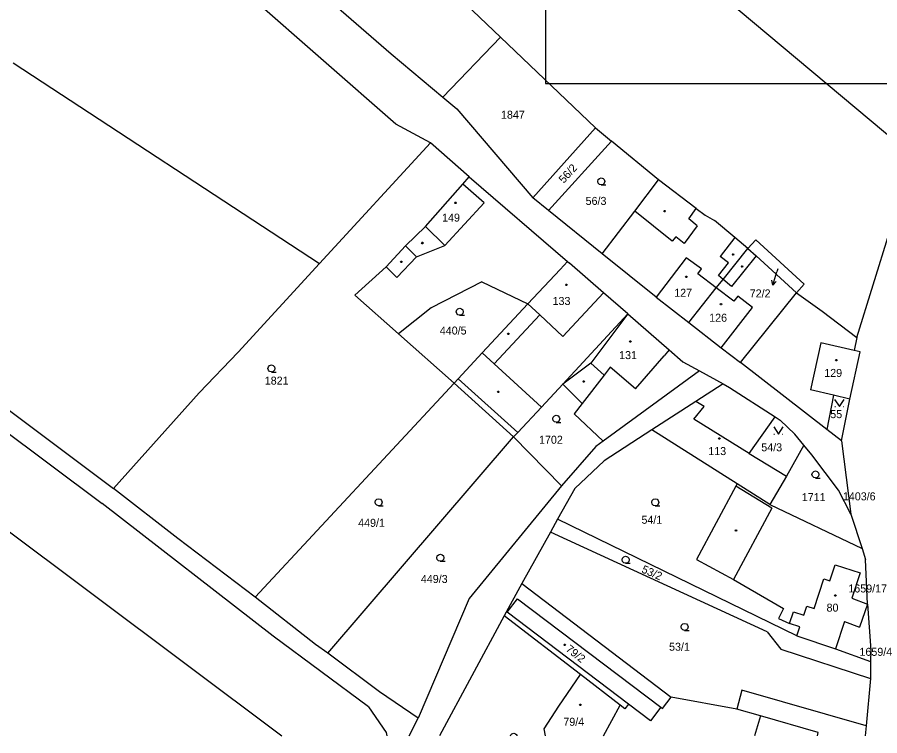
# Model space of a CAD drawing. Extents: x -801853 to -800578, y -1017479 to -1016338.
# Drawn here: x -801671.4 to -801488.1, y -1017477.7 to -1017325 of the extents above; entities that cross this region are included whole.
import ezdxf

# ---------------------------------------------------------------- set-up
doc = ezdxf.new("R2010")
doc.units = 0
for name, color, linetype in [('Default', 7, 'Continuous'), ('KN_HRANICE', 7, 'Continuous'), ('KN_KULTURY', 7, 'Continuous'), ('KN_PARCELY', 7, 'Continuous'), ('KN_SLUCKY', 7, 'Continuous'), ('LEGENDA', 7, 'Continuous')]:
    doc.layers.add(name, color=color, linetype=linetype)

# ---------------------------------------------------------------- blocks, each defined once
blk = doc.blocks.new('304')
at = {"layer": 'Default'}
blk.add_lwpolyline([(0, 0), (-0.38, 0.1), (-0.65, 0.37), (-0.75, 0.74), (-0.65, 1.11), (-0.38, 1.38), (-0.01, 1.48), (0.36, 1.38), (0.63, 1.11), (0.73, 0.73), (0.63, 0.35), (0.36, 0.08), (-0.02, -0.02), (0.98, -0.02)], dxfattribs=at)
blk = doc.blocks.new('314')
at = {"layer": 'Default'}
for p, q in [((-0.95, 0), (-0.85, 0)), ((0.85, 0), (0.95, 0))]:
    blk.add_line(p, q, dxfattribs=at)
blk.add_lwpolyline([(-1, 1.5), (0, 0), (1, 1.5)], dxfattribs=at)
blk = doc.blocks.new('NAHRADNI_SYMBOL')
at = {"layer": 'Default'}
blk.add_lwpolyline([(0.09, 0.15), (0.18, 0), (0.09, -0.15), (-0.09, -0.15), (-0.18, 0), (-0.09, 0.15), (0.09, 0.15)], dxfattribs=at)
blk = doc.blocks.new('10292')
at = {"layer": 'Default'}
blk.add_line((0, 3), (0, 0), dxfattribs=at)
blk.add_lwpolyline([(-0.5, 2), (0, 3), (0.5, 2)], dxfattribs=at)
blk = doc.blocks.new('402')
at = {"layer": 'Default'}
blk.add_lwpolyline([(0.09, 0.15), (0.18, 0), (0.09, -0.15), (-0.09, -0.15), (-0.18, 0), (-0.09, 0.15), (0.09, 0.15)], dxfattribs=at)

msp = doc.modelspace()

# ---------------------------------------------------------------- linework, layer by layer
at = {"layer": 'KN_HRANICE'}
for p, q in [((-801619.51, -1017238.39), (-801481.95, -1017353.71)), ((-801617.81, -1017310.3), (-801591.97, -1017332.75)), ((-801802.71, -1017316.54), (-801653.38, -1017428.3)), ((-801568.75, -1017329.21), (-801579.02, -1017319.41)), ((-801590.96, -1017347.71), (-801622.51, -1017320.08)), ((-801568.75, -1017329.21), (-801580.94, -1017341.98)), ((-801548.54, -1017348.49), (-801568.75, -1017329.21)), ((-801591.97, -1017332.75), (-801580.94, -1017341.98)), ((-801771.82, -1017334.66), (-801650.93, -1017425.14)), ((-801672.29, -1017334.66), (-801607.17, -1017377.34)), ((-801580.94, -1017341.98), (-801577.98, -1017344.46)), ((-801577.98, -1017344.46), (-801561.84, -1017363.38)), ((-801583.62, -1017351.71), (-801590.96, -1017347.71)), ((-801561.84, -1017363.38), (-801548.54, -1017348.49)), ((-801548.54, -1017348.49), (-801545.1, -1017351.32)), ((-801607.17, -1017377.34), (-801583.62, -1017351.71)), ((-801575.39, -1017358.89), (-801583.62, -1017351.71)), ((-801558.54, -1017366.04), (-801545.1, -1017351.32)), ((-801535.15, -1017359.53), (-801545.1, -1017351.32)), ((-801576.74, -1017360.44), (-801575.39, -1017358.89)), ((-801575.39, -1017358.89), (-801554.48, -1017376.92)), ((-801540.19, -1017366.17), (-801535.15, -1017359.53)), ((-801527.11, -1017365.64), (-801535.15, -1017359.53)), ((-801584.63, -1017369.48), (-801576.74, -1017360.44)), ((-801558.54, -1017366.04), (-801561.84, -1017363.38)), ((-801547.08, -1017375.26), (-801558.54, -1017366.04)), ((-801547.08, -1017375.26), (-801540.19, -1017366.17)), ((-801527.11, -1017365.64), (-801525.25, -1017367.08)), ((-801525.25, -1017367.08), (-801523.25, -1017368.15)), ((-801518.94, -1017371.78), (-801523.25, -1017368.15)), ((-801588.89, -1017373.59), (-801584.63, -1017369.48)), ((-801493.03, -1017393.07), (-801486.04, -1017370.69)), ((-801516.17, -1017374.11), (-801518.94, -1017371.78)), ((-801514.48, -1017372.27), (-801516.17, -1017374.11)), ((-801514.48, -1017372.27), (-801504.16, -1017381.72)), ((-801592.99, -1017378.06), (-801588.89, -1017373.59)), ((-801521.42, -1017380.69), (-801516.17, -1017374.11)), ((-801516.17, -1017374.11), (-801514.41, -1017375.72)), ((-801535.63, -1017384.47), (-801547.08, -1017375.26)), ((-801514.41, -1017375.72), (-801505.85, -1017383.57)), ((-801624.47, -1017396.18), (-801607.17, -1017377.34)), ((-801599.68, -1017384.03), (-801592.99, -1017378.06)), ((-801556.07, -1017378.59), (-801554.48, -1017376.92)), ((-801554.48, -1017376.92), (-801554.09, -1017377.25)), ((-801546.85, -1017383.57), (-801554.09, -1017377.25)), ((-801562.88, -1017385.9), (-801556.07, -1017378.59)), ((-801572.67, -1017381.19), (-801583.43, -1017386.73)), ((-801572.67, -1017381.19), (-801562.88, -1017385.9)), ((-801522.87, -1017382.51), (-801521.42, -1017380.69)), ((-801504.16, -1017381.72), (-801505.85, -1017383.57)), ((-801541.65, -1017388.03), (-801546.85, -1017383.57)), ((-801528.72, -1017389.84), (-801522.87, -1017382.51)), ((-801517.7, -1017398.38), (-801505.85, -1017383.57)), ((-801505.85, -1017383.57), (-801500.35, -1017387.46)), ((-801590.38, -1017392.28), (-801599.68, -1017384.03)), ((-801535.63, -1017384.47), (-801528.72, -1017389.84)), ((-801583.43, -1017386.73), (-801590.38, -1017392.28)), ((-801572.59, -1017396.33), (-801562.88, -1017385.9)), ((-801555.48, -1017402.95), (-801541.65, -1017388.03)), ((-801541.65, -1017388.03), (-801532.86, -1017395.69)), ((-801500.35, -1017387.46), (-801493.03, -1017393.07)), ((-801528.72, -1017389.84), (-801521.8, -1017395.21)), ((-801578.57, -1017402.75), (-801590.38, -1017392.28)), ((-801493.03, -1017393.07), (-801493.56, -1017395.81)), ((-801632.76, -1017404.81), (-801624.47, -1017396.18)), ((-801577.72, -1017401.84), (-801572.59, -1017396.33)), ((-801532.86, -1017395.69), (-801529.98, -1017398.2)), ((-801521.8, -1017395.21), (-801517.7, -1017398.38)), ((-801494.46, -1017406.11), (-801492.26, -1017396.11)), ((-801492.26, -1017396.11), (-801493.56, -1017395.81)), ((-801529.98, -1017398.2), (-801526.45, -1017400.14)), ((-801526.45, -1017400.14), (-801546.89, -1017415.08)), ((-801526.45, -1017400.14), (-801521.42, -1017402.91)), ((-801499.39, -1017412.56), (-801517.7, -1017398.38)), ((-801717.22, -1017401.3), (-801615.2, -1017477.65)), ((-801578.57, -1017402.75), (-801577.72, -1017401.84)), ((-801578.57, -1017402.75), (-801620.86, -1017448.21)), ((-801578.57, -1017402.75), (-801565.92, -1017414.14)), ((-801560.03, -1017407.86), (-801555.48, -1017402.95)), ((-801551.33, -1017407.06), (-801555.48, -1017402.95)), ((-801521.42, -1017402.91), (-801527.19, -1017406.63)), ((-801521.42, -1017402.91), (-801520.08, -1017403.65)), ((-801520.08, -1017403.65), (-801510.35, -1017409.92)), ((-801650.93, -1017425.14), (-801632.76, -1017404.81)), ((-801497.98, -1017405.3), (-801499.39, -1017412.56)), ((-801494.46, -1017406.11), (-801497.98, -1017405.3)), ((-801551.33, -1017407.06), (-801553.03, -1017409.26)), ((-801527.19, -1017406.63), (-801536.56, -1017412.68)), ((-801496.25, -1017414.99), (-801494.46, -1017406.11)), ((-801565.05, -1017413.25), (-801560.03, -1017407.86)), ((-801553.03, -1017409.26), (-801546.89, -1017415.08)), ((-801515.86, -1017417.69), (-801510.35, -1017409.92)), ((-801510.35, -1017409.92), (-801509.28, -1017410.61)), ((-801506.17, -1017413.59), (-801509.28, -1017410.61)), ((-801536.56, -1017412.68), (-801546.71, -1017419.24)), ((-801518.43, -1017424.13), (-801536.56, -1017412.68)), ((-801496.25, -1017414.99), (-801499.39, -1017412.56)), ((-801605.43, -1017460.13), (-801565.92, -1017414.14)), ((-801565.92, -1017414.14), (-801565.05, -1017413.25)), ((-801565.92, -1017414.14), (-801555.75, -1017424.58)), ((-801504.24, -1017415.93), (-801506.17, -1017413.59)), ((-801548.47, -1017416.23), (-801555.75, -1017424.58)), ((-801546.89, -1017415.08), (-801548.47, -1017416.23)), ((-801504.24, -1017415.93), (-801507.97, -1017422.53)), ((-801502.53, -1017418), (-801504.24, -1017415.93)), ((-801496.25, -1017414.99), (-801494.3, -1017430.54)), ((-801515.86, -1017417.69), (-801507.97, -1017422.53)), ((-801496.87, -1017425.51), (-801502.53, -1017418)), ((-801546.71, -1017419.24), (-801552.91, -1017425.1)), ((-801507.97, -1017422.53), (-801511.47, -1017428.53)), ((-801637.26, -1017435.75), (-801650.93, -1017425.14)), ((-801555.75, -1017424.58), (-801575.39, -1017448.51)), ((-801552.91, -1017425.1), (-801556.57, -1017431.67)), ((-801518.7, -1017424.64), (-801527.1, -1017440.22)), ((-801518.43, -1017424.13), (-801518.7, -1017424.64)), ((-801511.47, -1017428.53), (-801518.43, -1017424.13)), ((-801494.3, -1017430.54), (-801496.87, -1017425.51)), ((-801617.04, -1017456.51), (-801653.38, -1017428.3)), ((-801511.47, -1017428.53), (-801491.9, -1017437.9)), ((-801494.3, -1017430.54), (-801491.9, -1017437.9)), ((-801556.57, -1017431.67), (-801558.1, -1017434.4)), ((-801505.75, -1017456.45), (-801556.57, -1017431.67)), ((-801558.1, -1017434.4), (-801564.2, -1017445.34)), ((-801512.08, -1017455.55), (-801558.1, -1017434.4)), ((-801620.86, -1017448.21), (-801637.26, -1017435.75)), ((-801491.9, -1017437.9), (-801491.16, -1017440.19)), ((-801527.1, -1017440.22), (-801519.19, -1017444.45)), ((-801490.73, -1017449.68), (-801491.16, -1017440.19)), ((-801564.2, -1017445.34), (-801567.91, -1017452.2)), ((-801564.2, -1017445.34), (-801532.43, -1017469.46)), ((-801519.19, -1017444.45), (-801508.59, -1017450.64)), ((-801608.02, -1017458.26), (-801620.86, -1017448.21)), ((-801575.39, -1017448.51), (-801586.22, -1017473.94)), ((-801508.59, -1017450.64), (-801509.67, -1017452.75)), ((-801490.73, -1017449.68), (-801490.02, -1017459.44)), ((-801567.91, -1017452.2), (-801581.66, -1017477.65)), ((-801551.71, -1017464.66), (-801567.91, -1017452.2)), ((-801509.67, -1017452.75), (-801507.29, -1017453.78)), ((-801505.11, -1017454.5), (-801507.29, -1017453.78)), ((-801505.75, -1017456.45), (-801505.11, -1017454.5)), ((-801596.78, -1017471.51), (-801617.04, -1017456.51)), ((-801512.08, -1017455.55), (-801509.17, -1017459.29)), ((-801505.75, -1017456.45), (-801497.54, -1017459.17)), ((-801605.43, -1017460.13), (-801608.02, -1017458.26)), ((-801594.4, -1017468.3), (-801605.43, -1017460.13)), ((-801509.17, -1017459.29), (-801490.11, -1017465.48)), ((-801497.54, -1017459.17), (-801490.11, -1017461.87)), ((-801490.02, -1017459.44), (-801490.11, -1017461.87)), ((-801490.11, -1017461.87), (-801490.11, -1017465.48)), ((-801556.33, -1017471.36), (-801551.71, -1017464.66)), ((-801543.26, -1017471.16), (-801551.71, -1017464.66)), ((-801490.11, -1017465.48), (-801491, -1017475.58)), ((-801586.22, -1017473.94), (-801594.4, -1017468.3)), ((-801534.26, -1017471.87), (-801532.43, -1017469.46)), ((-801518.51, -1017471.99), (-801532.43, -1017469.46)), ((-801517.41, -1017467.99), (-801518.51, -1017471.99)), ((-801491, -1017475.58), (-801517.41, -1017467.99)), ((-801596.78, -1017471.51), (-801593.04, -1017476.93)), ((-801559.45, -1017476.19), (-801556.33, -1017471.36)), ((-801546.8, -1017477.65), (-801543.26, -1017471.16)), ((-801542.27, -1017471.92), (-801543.26, -1017471.16)), ((-801541.51, -1017470.93), (-801542.27, -1017471.92)), ((-801536.86, -1017474.46), (-801541.51, -1017470.93)), ((-801534.66, -1017471.57), (-801536.86, -1017474.46)), ((-801534.66, -1017471.57), (-801534.26, -1017471.87)), ((-801513.5, -1017473.44), (-801518.51, -1017471.99)), ((-801513.5, -1017473.44), (-801514.73, -1017477.65)), ((-801588.14, -1017477.65), (-801586.22, -1017473.94)), ((-801593.04, -1017476.93), (-801592.86, -1017477.65)), ((-801559.13, -1017477.65), (-801559.45, -1017476.19)), ((-801491, -1017475.58), (-801491.26, -1017477.65))]:
    msp.add_line(p, q, dxfattribs=at)
at = {"layer": 'KN_KULTURY'}
msp.add_lwpolyline([(-801566.6, -1017477.65), (-801566.55, -1017477.48), (-801566.28, -1017477.21), (-801565.91, -1017477.11), (-801565.54, -1017477.21), (-801565.27, -1017477.48), (-801565.23, -1017477.65)], dxfattribs=at)
at = {"layer": 'KN_PARCELY'}
msp.add_line((-801509.8, -1017378.42), (-801510, -1017379.07), dxfattribs=at)
at = {"layer": 'KN_SLUCKY'}
for p, q in [((-801572.2, -1017364.41), (-801576.74, -1017360.44)), ((-801572.2, -1017364.41), (-801580.56, -1017373.52)), ((-801532.21, -1017372.54), (-801540.19, -1017366.17)), ((-801528.73, -1017367.8), (-801527.11, -1017365.64)), ((-801526.9, -1017369.29), (-801528.73, -1017367.8)), ((-801584.63, -1017369.48), (-801580.56, -1017373.52)), ((-801526.9, -1017369.29), (-801529.68, -1017373.09)), ((-801531.47, -1017371.63), (-801532.21, -1017372.54)), ((-801529.68, -1017373.09), (-801531.47, -1017371.63)), ((-801518.94, -1017371.78), (-801522.04, -1017375.81)), ((-801588.89, -1017373.59), (-801586.56, -1017375.88)), ((-801586.56, -1017375.88), (-801580.56, -1017373.52)), ((-801586.56, -1017375.88), (-801590.78, -1017380.31)), ((-801529.25, -1017376.14), (-801535.63, -1017384.47)), ((-801525.99, -1017378.48), (-801529.25, -1017376.14)), ((-801520.3, -1017377.18), (-801522.04, -1017375.81)), ((-801514.41, -1017375.72), (-801519.61, -1017382.22)), ((-801592.99, -1017378.06), (-801590.78, -1017380.31)), ((-801522.39, -1017379.87), (-801520.3, -1017377.18)), ((-801526.82, -1017379.48), (-801525.99, -1017378.48)), ((-801522.87, -1017382.51), (-801526.82, -1017379.48)), ((-801521.42, -1017380.69), (-801522.39, -1017379.87)), ((-801519.61, -1017382.22), (-801521.42, -1017380.69)), ((-801546.85, -1017383.57), (-801555.5, -1017392.82)), ((-801519.17, -1017385.35), (-801522.87, -1017382.51)), ((-801518.31, -1017384.26), (-801519.17, -1017385.35)), ((-801515.18, -1017386.69), (-801518.31, -1017384.26)), ((-801560.37, -1017388.25), (-801562.88, -1017385.9)), ((-801521.8, -1017395.21), (-801515.18, -1017386.69)), ((-801570.07, -1017398.64), (-801560.37, -1017388.25)), ((-801555.5, -1017392.82), (-801560.37, -1017388.25)), ((-801541.65, -1017388.03), (-801549.55, -1017398.5)), ((-801500.66, -1017394.18), (-801502.86, -1017404.18)), ((-801493.56, -1017395.81), (-801500.66, -1017394.18)), ((-801570.07, -1017398.64), (-801572.59, -1017396.33)), ((-801532.86, -1017395.69), (-801533.91, -1017396.9)), ((-801540.01, -1017403.98), (-801533.91, -1017396.9)), ((-801560.03, -1017407.86), (-801570.07, -1017398.64)), ((-801549.55, -1017398.5), (-801555.48, -1017402.95)), ((-801549.55, -1017398.5), (-801546.7, -1017401.04)), ((-801545.41, -1017399.37), (-801546.7, -1017401.04)), ((-801540.01, -1017403.98), (-801545.41, -1017399.37)), ((-801565.05, -1017413.25), (-801577.72, -1017401.84)), ((-801546.7, -1017401.04), (-801551.33, -1017407.06)), ((-801497.98, -1017405.3), (-801502.86, -1017404.18)), ((-801525.46, -1017407.68), (-801527.19, -1017406.63)), ((-801527.6, -1017410.39), (-801525.46, -1017407.68)), ((-801515.86, -1017417.69), (-801527.6, -1017410.39)), ((-801511.05, -1017429.33), (-801518.7, -1017424.64)), ((-801511.05, -1017429.33), (-801519.19, -1017444.45)), ((-801498.77, -1017444.75), (-801497.63, -1017441.33)), ((-801497.63, -1017441.33), (-801492.28, -1017443.05)), ((-801492.28, -1017443.05), (-801494.03, -1017448.42)), ((-801502.08, -1017450.61), (-801500, -1017444.34)), ((-801500, -1017444.34), (-801498.77, -1017444.75)), ((-801567.28, -1017451.37), (-801565.08, -1017448.53)), ((-801565.08, -1017448.53), (-801534.66, -1017471.57)), ((-801494.03, -1017448.42), (-801490.73, -1017449.68)), ((-801541.51, -1017470.93), (-801567.28, -1017451.37)), ((-801507.29, -1017453.78), (-801506.47, -1017451.31)), ((-801506.47, -1017451.31), (-801504.29, -1017452.03)), ((-801504.29, -1017452.03), (-801503.64, -1017450.09)), ((-801503.64, -1017450.09), (-801502.08, -1017450.61)), ((-801490.73, -1017449.68), (-801492.46, -1017454.58)), ((-801495.65, -1017453.37), (-801497.54, -1017459.17)), ((-801495.65, -1017453.37), (-801492.46, -1017454.58)), ((-801501.2, -1017476.98), (-801513.5, -1017473.44)), ((-801501.39, -1017477.65), (-801501.2, -1017476.98))]:
    msp.add_line(p, q, dxfattribs=at)
at = {"layer": 'LEGENDA'}
msp.add_lwpolyline([(-801559.16, -1017339.08), (-800718.16, -1017339.08), (-800718.16, -1016745.08), (-801559.16, -1016745.08)], close=True, dxfattribs=at)

# ---------------------------------------------------------------- block references
at = {"layer": 'KN_KULTURY'}
for name, p in [('304', (-801547.29, -1017360.61)), ('402', (-801578.28, -1017364.41)), ('402', (-801533.86, -1017366.18)), ('402', (-801585.3, -1017372.96)), ('402', (-801519.28, -1017375.38)), ('402', (-801589.78, -1017376.97)), ('402', (-801517.38, -1017377.96)), ('402', (-801554.7, -1017381.85)), ('402', (-801529.23, -1017380.16)), ('304', (-801577.38, -1017388.3)), ('402', (-801521.86, -1017385.94)), ('402', (-801567.06, -1017392.28)), ('402', (-801541.13, -1017393.89)), ('402', (-801497.34, -1017397.85)), ('304', (-801617.39, -1017400.35)), ('402', (-801551.02, -1017402.39)), ('402', (-801569.2, -1017404.58)), ('314', (-801496.71, -1017407.69)), ('304', (-801556.85, -1017411.05)), ('314', (-801509.66, -1017413.55)), ('402', (-801522.21, -1017414.48)), ('304', (-801501.78, -1017422.88)), ('304', (-801594.6, -1017428.78)), ('304', (-801535.81, -1017428.8)), ('402', (-801518.66, -1017434.02)), ('304', (-801581.49, -1017440.56)), ('304', (-801542.11, -1017441)), ('402', (-801497.57, -1017447.84)), ('304', (-801529.58, -1017455.26)), ('402', (-801555.05, -1017458.31)), ('NAHRADNI_SYMBOL', (-801551.76, -1017471.1))]:
    msp.add_blockref(name, p, dxfattribs=at)
at = {"layer": 'KN_PARCELY', "rotation": 162.949197}
msp.add_blockref('10292', (-801510, -1017379.07), dxfattribs=at)

# ---------------------------------------------------------------- texts
at = {"layer": 'KN_PARCELY'}
for s, height, p in [('1847', 1.7, (-801568.61, -1017346.56)), ('56/3', 1.7, (-801550.63, -1017364.87)), ('149', 1.7, (-801581.13, -1017368.42)), ('72/2', 0.1, (-801510, -1017378.42)), ('127', 1.7, (-801531.8, -1017384.39)), ('72/2', 1.7, (-801515.76, -1017384.52)), ('133', 1.7, (-801557.65, -1017386.13)), ('126', 1.7, (-801524.37, -1017389.69)), ('440/5', 1.7, (-801581.61, -1017392.41)), ('131', 1.7, (-801543.51, -1017397.63)), ('129', 1.7, (-801499.92, -1017401.42)), ('1821', 1.7, (-801618.81, -1017403.05)), ('55', 1.7, (-801498.65, -1017410.17)), ('1702', 1.7, (-801560.53, -1017415.61)), ('113', 1.7, (-801524.56, -1017418.02)), ('54/3', 1.7, (-801513.3, -1017417.22)), ('1711', 1.7, (-801504.7, -1017427.81)), ('1403/6', 1.7, (-801495.96, -1017427.64)), ('54/1', 1.7, (-801538.76, -1017432.61)), ('449/1', 1.7, (-801598.96, -1017433.26)), ('449/3', 1.7, (-801585.64, -1017445.19)), ('1659/17', 1.7, (-801494.8, -1017447.21)), ('80', 1.7, (-801499.43, -1017451.28)), ('53/1', 1.7, (-801532.9, -1017459.59)), ('1659/4', 1.7, (-801492.44, -1017460.67)), ('79/4', 1.7, (-801555.36, -1017475.53))]:
    msp.add_text(s, height=height, dxfattribs=at).set_placement(p)
for s, rotation, p in [('56/2', 47.785, (-801555.26, -1017360.4)), ('53/2', 336.613, (-801538.89, -1017442.9)), ('79/2', 321.716, (-801555, -1017459.52))]:
    msp.add_text(s, height=1.7, rotation=rotation, dxfattribs=at).set_placement(p)

doc.saveas('drawing.dxf')
